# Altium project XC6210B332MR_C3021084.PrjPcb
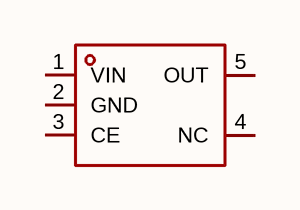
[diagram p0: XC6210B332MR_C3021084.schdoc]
1 sheet, 1 parts. Net scope: global (net labels, ports and power ports of the same name join across sheets).

## Sheet XC6210B332MR_C3021084.schdoc
size 127 x 101 mm

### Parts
U?  xc6210b332mr  [SOT-23-5_L2.9-W1.6-P0.95-LS2.8-BR]  (value not drawn)

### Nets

Not connected (* = marked no-connect by the designer): U? 1(VIN) 2(GND) 3(CE) 4(NC) 5(OUT)

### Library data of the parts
U? = xc6210b332mr: 输出极性:正极;工作电压:5.5V;输出电压:3.3V;输出电流:800mA;电源纹波抑制比(PSRR):70dB@(1kHz);输出类型:固定;; Manufacturer: TECH PUBLIC(台舟); Symbol: XC6210B332MR_C3021084; AddInBom: yes; ModelId: 7ba65df16e7b4570af156e925f9c37fe; ModelTransform: 114.173,114.173,0,90,0,0,0,0,0; Output Configuration: 正极; Voltage - Supply: 5.5V; Output Voltage: 3.3V; Output Current: 800mA; Voltage Dropout: 450mV@(800mA); standby current: 25uA; Output Type: 固定; Number of Outputs: 1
